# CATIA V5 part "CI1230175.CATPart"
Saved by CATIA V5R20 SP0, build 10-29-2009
Part number: CI1230175
Bounding box of the stored display mesh (mm): x -29 to 29, y -25.653 to 220, z -33.725 to 34.027
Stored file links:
  C:\Users\Raffaele\Desktop\3D X SITO CF\BOLEX\19-INCLINED ASSEMBLY REF_CI\CI1230175.CATPart
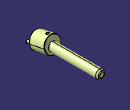
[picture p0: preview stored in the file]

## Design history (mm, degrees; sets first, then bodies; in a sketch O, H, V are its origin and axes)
Set1
  DatumSurface1 to DatumSurface16 "MANIFOLD_SOLID_BREP #395"
  DatumSurface17 to DatumSurface39 "MANIFOLD_SOLID_BREP #1144"
Body1 (main body)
